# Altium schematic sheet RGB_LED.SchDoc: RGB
size A4; CompanyName: Arduino srl; DrawnBy: Silvio Navaretti; DocumentNumber: ASX00039; SheetNumber: 7; SheetTotal: 8; RevAuthor: Silvio Navaretti
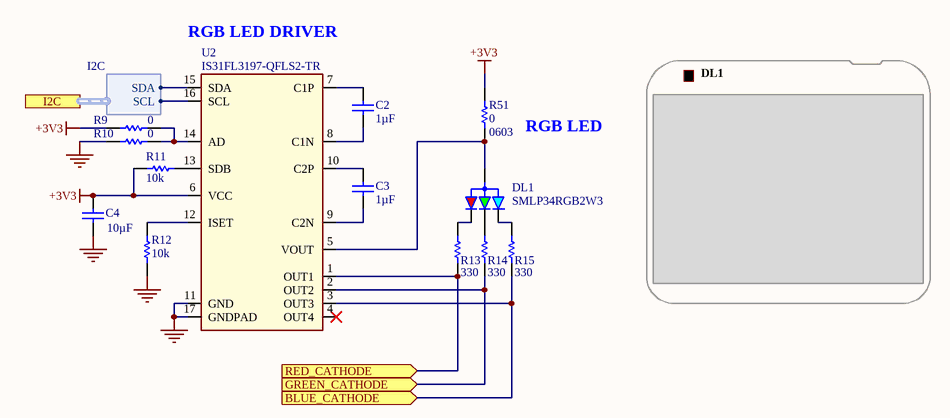
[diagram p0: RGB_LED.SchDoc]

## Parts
C2  value 1µF  [CAP-0603]  (hidden comment: TMK107BJ105MAHT)
C3  value 1µF  [CAP-0603]  (hidden comment: TMK107BJ105MAHT)
C4  value 10µF  [CAP-0603]  (hidden comment: GRM188R61C106KAALD)
DL1  SMLP34RGB2W3  [SMLP34RGB2W]
R9  value 0  [RES-0603]  (hidden comment: CRCW06030000Z0EAC)
R10  value 0  [RES-0603]  (hidden comment: CRCW06030000Z0EAC)
R11  value 10k  [RES-0603]  (hidden comment: CRCW060310K0JNEAC)
R12  value 10k  [RES-0603]  (hidden comment: CRCW060310K0JNEAC)
R13  value 330  [RES-0603]  (hidden comment: CRCW0603330RFKEAC)
R14  value 330  [RES-0603]  (hidden comment: CRCW0603330RFKEAC)
R15  value 330  [RES-0603]  (hidden comment: CRCW0603330RFKEAC)
R51  value 0  Case Code (Imperial): 0603  [RES-0603]  (hidden comment: CRCW06030000Z0EAC)
U2  IS31FL3197-QFLS2-TR  [PQFN65P400X400X80_HS-17N]

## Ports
BLUE_CATHODE (in), GREEN_CATHODE (in), I2C (harness I2C), RED_CATHODE (in)

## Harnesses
I2C: SDA, SCL

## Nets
+3V3: C4.2 R9.2 R11.2 R51.2 U2.6(VCC)
GND: C4.1 R10.2 R12.1 U2.11(GND) U2.17(GNDPAD)
BLUE_CATHODE: R15.1 U2.3(OUT3) ; port BLUE_CATHODE
GREEN_CATHODE: R14.1 U2.2(OUT2) ; port GREEN_CATHODE
RED_CATHODE: R13.1 U2.1(OUT1) ; port RED_CATHODE
NetC2_1: C2.1 U2.8(C1N)
NetC2_2: C2.2 U2.7(C1P)
NetC3_1: C3.1 U2.9(C2N)
NetC3_2: C3.2 U2.10(C2P)
NetDL1_1: DL1.1(ANODE) R51.1 U2.5(VOUT)
NetDL1_2: DL1.2(RED_C) R13.2
NetDL1_3: DL1.3(BLUE_C) R15.2
NetDL1_4: DL1.4(GREEN_C) R14.2
NetR9_1: R9.1 R10.1 U2.14(AD)
NetR11_1: R11.1 U2.13(SDB)
NetR12_2: R12.2 U2.12(ISET)
NetU2_15: U2.15(SDA) ; port I2C.SDA
NetU2_16: U2.16(SCL) ; port I2C.SCL

Not connected (* = marked no-connect by the designer): U2 4(OUT4)*

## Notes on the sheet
- RGB LED DRIVER
- DL1
- RGB LED

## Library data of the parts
C2 C3 = C0077-A.10: CAP CHIP 0603 1UF 25V X5R 20%; Manufacturer: Taiyo Yuden; Code Arduino: C0077
C4 = C0071-A.9: CAP CHIP 0603 10uF 16V X5R 10%; Manufacturer: Murata; Code Arduino: C0071
DL1 = L0014-A.10: LED RGB DIFFUSED PICOLED SMD; Manufacturer: ROHM Semiconductor; Code Arduino: A5469; Forward Current: 20mA; Lens Style: Rectangular; Dominant Wavelength: 470nm; Forward Voltage: 3V; Test Current: 5mA; Luminous Intensity: 45mcd; Lens Color: White
R9 R10 R51 = R0096-A.13: RES CHIP 0603 0R 1/10W; Manufacturer: Vishay; Power: 100mW; Tolerance: J; Code Arduino: 0233
R11 = R0090-A.13: RES CHIP 0603 10k 5% 1/10W B.5k; Manufacturer: Vishay; Power: 100mW; Code Arduino: 0028
R12 = R0090-A.13: RES CHIP 0603 10k 5% 1/10W B.5k; Manufacturer: Vishay; Code Arduino: 0028; Power: 100mW
R13-R15 = R0123-A.13: RES CHIP 0603 330R 1% 1/10W; Manufacturer: Vishay; Power: 100mW; Code Arduino: 0049
U2 = U0285-A.1: IC LED DRIVER RGB W (4ch) charge pump self running QFN16; Manufacturer: Lumissil; Code Arduino: U0285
